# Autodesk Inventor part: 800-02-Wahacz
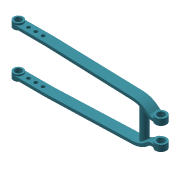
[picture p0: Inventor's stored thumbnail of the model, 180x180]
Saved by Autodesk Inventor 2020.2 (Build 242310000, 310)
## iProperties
Created: 2014-12
Part Number: 800-02-Wahacz
Material: Aluminium 6061
Document SubType Name: Modeling
Designer: F.Stasiak
Density: 2.7 g/cm^3
Appearance: Niebieska z odcieniem szarości
Mass: 188.706 g
Surface Area: 669.681 cm^2
Volume: 188.706 cm^3
Catalog Web Link: www.expertbooks.pl
Manager: www.cadconsulting.pl
Company: Fabian Stasiak CAD Consulting
Author: F.Stasiak
Subject: Zbiór ćwiczeń. Autodesk Inventor 2020. Kurs Professional
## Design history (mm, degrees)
node "Płaszczyzna konstrukcyjna1"
sketch "Szkic2"
  geometry: L1 (79.08, -14.077)-(79.08, 20.923); L2 (57.495, 64.949)-(49.08, 305.923); L3 (49.08, 305.923)-(49.08, 405.923); L4 (41.08, 405.923)-(41.08, 305.783); L5 (41.08, 305.783)-(49.5, 64.67); L6 (71.08, 17.314)-(71.08, -14.077); L7 (49.08, 405.923)-(41.08, 405.923); L8 (79.08, -14.077)-(71.08, -14.077); A1 r 60 centre (117.459, 67.043) between (57.495, 64.949) and (79.08, 20.923); A2 r 68 centre (117.459, 67.043) between (49.5, 64.67) and (71.08, 17.314); 1 further point
  constraints: 16 end point, 4 point on circle, 2 centre point, 2 vertical, 1 coincident, 1 horizontal, 1 parallel, 1 tangent, 3 other
  dimensions: "d0" = 35 distance of L1.start L1.end; "d3" = 60 radius of A1; "d4" = 2 deg angle of L1 L2; "d6" = 100 distance of L2.end L3.end; "d7" = 420 vertical distance of L3.end point (79.08, -14.077); "d8" = 30 horizontal distance of L1.end L3.end; "d9" = 8 distance between parallel lines of L2 L5
extrude "Wyciągnięcie proste1" new body sketch "Szkic2" stored distance "d10" = 30; taper "d11" = 0 deg
feature "Pochylenie ściany1" dims angle "d12" = -0.25 deg
fillet "Zaokrąglenie1"
fillet "Zaokrąglenie2" dims "d13" = 15
fillet "Zaokrąglenie4" dims "d15" = 15
fillet "Zaokrąglenie5" dims "d16" = 23
sketch "Szkic3"
  geometry: C1 r 15 at (10.248, 14.824); A1 r 15 centre (10.248, 14.824) between (25.248, 14.824) and (10.183, 29.824) reference; 1 further point
  constraints: 1 centre point, 1 coincident
  dimensions: "d18" = 30 diameter of C1
extrude "Wyciągnięcie proste2" join sketch "Szkic3" distance "d19" = 5; taper "d21" = 0 deg; dims "d20" = 12, "d22" = 0
sketch "Szkic4"
  geometry: C1 r 13.225 at (-86.915, 13.604); A1 r 13.225 centre (-86.915, 13.604) between (-86.972, 26.829) and (-86.972, 0.379) reference; 1 further point
  constraints: 1 centre point, 1 coincident, 1 concentric
extrude "Wyciągnięcie proste3" join sketch "Szkic4" distance "d24" = 5; taper "d26" = 0 deg; dims "d25" = 12, "d27" = 0
sketch "Szkic5"
  geometry: C1 r 15 at (0, 0) reference; C2 r 10 at (0, 0); 1 further point
  constraints: 1 centre point, 1 coincident
  dimensions: "d30" = 20 diameter of C2
extrude "Wyciągnięcie proste4" cut sketch "Szkic5" extent not by distance; stored distance "d31" = 5; taper "d32" = 0 deg
sketch "Szkic6"
  geometry: C1 r 13.225 at (0, 0) reference; C2 r 9 at (0, 0); 1 further point
  constraints: 1 centre point, 1 coincident
  dimensions: "d33" = 18 diameter of C2
extrude "Wyciągnięcie proste5" cut sketch "Szkic6" extent not by distance; stored distance "d34" = 5; taper "d35" = 0 deg
sketch "Szkic7"
  geometry: L1 (0, 0)-(0, 27.209) reference; L2 (-86.915, 13.604)-(0, 13.604); C1 r 13.225 at (-86.915, 13.604) reference; 4 further points
  constraints: 3 point on line, 2 end point, 1 midpoint
  dimensions: "d36" = 40 distance of point (-18.915, 13.604) point (-58.915, 13.604); "d37" = 28 distance of L2.start point (-58.915, 13.604); "d45" = 20 distance of point (-38.915, 13.604) point (-58.915, 13.604) (= 0.5 x d36)
hole "Otwór1" sketch "Szkic7" at (-58.915, 13.604), (-18.915, 13.604), (-38.915, 13.604) diameter "d38" = 10; stored, may be unused: countersink angle "d42" = 90 deg, drill point angle "d44" = 118 deg; dims "d39" = 6, "d40" = 4, "d41" = 2, "d43" = 8
node "Płaszczyzna konstrukcyjna2"
sketch "Szkic9"
  geometry: C1 r 10 at (45, 0); C2 r 10 at (0, 0) reference; 1 further point
  constraints: 1 centre point, 1 horizontal alignment
  dimensions: "d52" = 20 diameter of C1; "d53" = 45 distance of C2.centre C1.centre
extrude "Wyciągnięcie proste7" join sketch "Szkic9" stored distance "d54" = 96; taper "d55" = 0 deg
fillet "Zaokrąglenie9" dims "d56" = 3
mirror "Odbicie lustrzane1"
node "Bryła1"
node "Pętla rzutowana1"
other parameters: "d46" = 22.5
